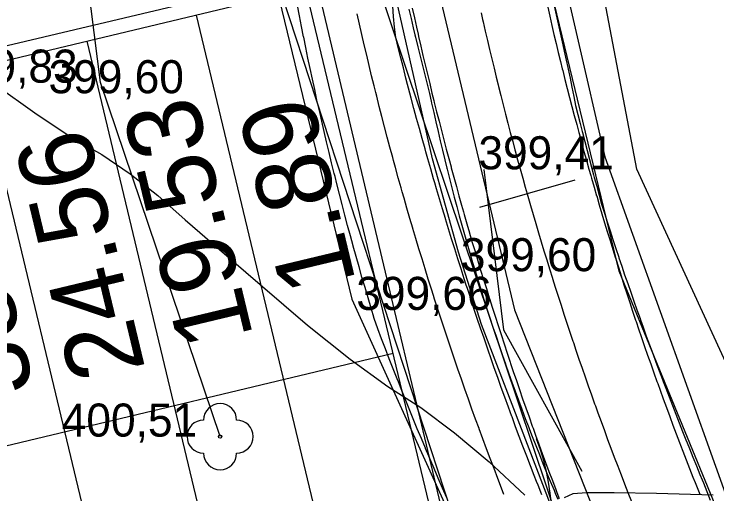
# Model space of a CAD drawing. Extents: x -574342 to -507939, y -1144044 to -1123894.
# Drawn here: x -508553.2 to -508531.96, y -1143248.56 to -1143234.06 of the extents above; entities that cross this region are included whole.
import ezdxf

# ---------------------------------------------------------------- set-up
doc = ezdxf.new("R2010")
doc.units = 0
for name, color, linetype in [('01_PARCELY_NAVRH_PC', 7, 'Continuous'), ('01_PARCELY_NAVRH_VHO', 7, 'Continuous'), ('01_PARCELY_NAVRH_ŽP', 7, 'Continuous'), ('1000', 7, 'Continuous'), ('21', 7, 'Continuous'), ('37', 7, 'Continuous'), ('42', 7, 'Continuous'), ('54', 7, 'Continuous'), ('55', 7, 'Continuous'), ('6', 7, 'Continuous'), ('62', 7, 'Continuous'), ('cesty', 7, 'Continuous'), ('Level 255', 7, 'Continuous'), ('SO 101_popis oblouku', 7, 'Continuous'), ('tab', 7, 'Continuous'), ('VRST HL', 7, 'Continuous')]:
    doc.layers.add(name, color=color, linetype=linetype)

msp = doc.modelspace()

# ---------------------------------------------------------------- linework, layer by layer
msp.add_lwpolyline([(-508538.692, -1143255.691), (-508544.119, -1143232.805), (-508565.304, -1143237.829), (-508559.878, -1143260.714)], close=True)
at = {"layer": '01_PARCELY_NAVRH_PC'}
msp.add_lwpolyline([(-508524.61, -1143277.77), (-508531.94, -1143260.32), (-508534.5, -1143254.93), (-508536.24, -1143250.83), (-508539.07, -1143243.44), (-508539.77, -1143241.25), (-508540.55, -1143238.43), (-508542.83, -1143228.38), (-508544.32, -1143217.47), (-508545.45, -1143205.07), (-508545.52, -1143198.58), (-508545.24, -1143191.32), (-508544.97, -1143188.3), (-508544.25, -1143181.83), (-508541.94, -1143173.53), (-508537.18, -1143176.51), (-508538.65, -1143182.46), (-508540.32, -1143193.28), (-508540.02, -1143209.35), (-508538.46, -1143221.35), (-508537.02, -1143231.11), (-508535.34, -1143238.37), (-508531.16, -1143250.06), (-508524.26, -1143263.08)], dxfattribs=at)
msp.add_lwpolyline([(-508524.61, -1143277.77), (-508531.94, -1143260.32), (-508534.5, -1143254.93), (-508536.24, -1143250.83), (-508539.07, -1143243.44), (-508539.77, -1143241.25), (-508540.55, -1143238.43), (-508542.83, -1143228.38), (-508544.32, -1143217.47), (-508545.45, -1143205.07), (-508545.52, -1143198.58), (-508545.24, -1143191.32), (-508544.97, -1143188.3), (-508544.25, -1143181.83), (-508541.94, -1143173.53), (-508537.18, -1143176.51), (-508538.65, -1143182.46), (-508540.32, -1143193.28), (-508540.02, -1143209.35), (-508538.46, -1143221.35), (-508537.02, -1143231.11), (-508535.34, -1143238.37), (-508531.16, -1143250.06), (-508524.26, -1143263.08)], dxfattribs=at)
at = {"layer": '01_PARCELY_NAVRH_VHO'}
msp.add_lwpolyline([(-508536.24, -1143250.83), (-508539.07, -1143243.44), (-508539.77, -1143241.25), (-508540.55, -1143238.43), (-508542.83, -1143228.38), (-508544.32, -1143217.47), (-508545.45, -1143205.07), (-508545.52, -1143198.58), (-508545.24, -1143191.32), (-508544.97, -1143188.3), (-508544.25, -1143181.83), (-508551.68, -1143170.14), (-508558.5, -1143170.32), (-508555.03, -1143173.64), (-508548.66, -1143186.8), (-508549.63, -1143198.15), (-508549.79, -1143203.71), (-508547.53, -1143223.9), (-508542.99, -1143242.68), (-508538.24, -1143253.15)], close=True, dxfattribs=at)
at = {"layer": '01_PARCELY_NAVRH_ŽP'}
msp.add_lwpolyline([(-508555.03, -1143173.64), (-508548.66, -1143186.8), (-508549.63, -1143198.15), (-508549.79, -1143203.71), (-508547.53, -1143223.9), (-508542.99, -1143242.68), (-508538.24, -1143253.15), (-508539.95, -1143255.3), (-508547.25, -1143258.62), (-508651.11, -1143191.46), (-508662.59, -1143152.85), (-508637.59, -1143153.08), (-508621.09, -1143158.13), (-508610.87, -1143164.96), (-508585.59, -1143176.01), (-508569.25, -1143175.97)], close=True, dxfattribs=at)
at = {"layer": '1000'}
for points in [[(-508540.12, -1143248.685), (-508540.25, -1143248.387), (-508540.379, -1143248.089), (-508540.507, -1143247.79), (-508540.634, -1143247.491), (-508540.761, -1143247.192), (-508540.765, -1143247.182), (-508540.886, -1143246.892), (-508541.011, -1143246.592), (-508541.134, -1143246.291), (-508541.257, -1143245.99), (-508541.379, -1143245.689), (-508541.5, -1143245.387), (-508541.584, -1143245.176), (-508541.621, -1143245.085), (-508541.74, -1143244.782), (-508541.858, -1143244.479), (-508541.976, -1143244.175), (-508542.092, -1143243.871), (-508542.208, -1143243.567), (-508542.315, -1143243.26), (-508542.349, -1143243.147), (-508542.409, -1143242.948), (-508542.501, -1143242.636), (-508542.592, -1143242.324), (-508542.683, -1143242.012), (-508542.772, -1143241.699), (-508542.86, -1143241.386), (-508542.947, -1143241.073), (-508542.949, -1143241.064), (-508543.032, -1143240.759), (-508543.117, -1143240.445), (-508543.2, -1143240.131), (-508543.251, -1143239.937), (-508543.282, -1143239.816), (-508543.364, -1143239.501), (-508543.444, -1143239.186), (-508543.498, -1143238.968), (-508543.523, -1143238.871), (-508543.6, -1143238.555), (-508543.677, -1143238.239), (-508543.752, -1143237.923), (-508543.827, -1143237.607), (-508543.9, -1143237.29), (-508543.972, -1143236.974), (-508543.998, -1143236.861), (-508544.043, -1143236.657), (-508544.113, -1143236.339), (-508544.182, -1143236.022), (-508544.249, -1143235.704), (-508544.316, -1143235.386), (-508544.381, -1143235.068), (-508544.445, -1143234.75), (-508544.447, -1143234.743), (-508544.508, -1143234.431), (-508544.57, -1143234.112), (-508544.631, -1143233.793)], [(-508537.248, -1143248.595), (-508537.28, -1143248.512), (-508537.364, -1143248.301), (-508537.406, -1143248.192), (-508537.479, -1143248.007), (-508537.593, -1143247.712), (-508537.706, -1143247.418), (-508537.818, -1143247.122), (-508537.929, -1143246.827), (-508538.04, -1143246.531), (-508538.15, -1143246.235), (-508538.154, -1143246.225), (-508538.259, -1143245.939), (-508538.367, -1143245.642), (-508538.474, -1143245.345), (-508538.58, -1143245.048), (-508538.685, -1143244.75), (-508538.79, -1143244.452), (-508538.862, -1143244.243), (-508538.893, -1143244.154), (-508538.996, -1143243.855), (-508539.098, -1143243.556), (-508539.199, -1143243.257), (-508539.299, -1143242.957), (-508539.398, -1143242.657), (-508539.496, -1143242.357), (-508539.532, -1143242.248), (-508539.594, -1143242.057), (-508539.69, -1143241.756), (-508539.786, -1143241.455), (-508539.88, -1143241.154), (-508539.974, -1143240.852), (-508540.067, -1143240.551), (-508540.159, -1143240.248), (-508540.162, -1143240.24), (-508540.25, -1143239.946), (-508540.341, -1143239.643), (-508540.43, -1143239.34), (-508540.485, -1143239.154), (-508540.519, -1143239.037), (-508540.606, -1143238.734), (-508540.693, -1143238.43), (-508540.752, -1143238.219), (-508540.779, -1143238.126), (-508540.864, -1143237.822), (-508540.948, -1143237.517), (-508541.031, -1143237.212), (-508541.113, -1143236.907), (-508541.194, -1143236.602), (-508541.274, -1143236.296), (-508541.303, -1143236.187), (-508541.354, -1143235.99), (-508541.432, -1143235.684), (-508541.51, -1143235.378), (-508541.587, -1143235.071), (-508541.663, -1143234.765), (-508541.7, -1143234.449), (-508541.727, -1143234.131), (-508541.727, -1143234.125), (-508541.75, -1143233.813)], [(-508541.266, -1143233.904), (-508541.2, -1143234.189), (-508541.134, -1143234.474), (-508541.085, -1143234.681), (-508541.067, -1143234.759), (-508540.999, -1143235.043), (-508540.93, -1143235.328), (-508540.859, -1143235.612), (-508540.789, -1143235.895), (-508540.717, -1143236.179), (-508540.644, -1143236.462), (-508540.59, -1143236.693), (-508540.578, -1143236.747), (-508540.515, -1143237.033), (-508540.451, -1143237.319), (-508540.386, -1143237.604), (-508540.319, -1143237.889), (-508540.252, -1143238.173), (-508540.182, -1143238.458), (-508540.119, -1143238.713), (-508540.112, -1143238.742), (-508540.041, -1143239.026), (-508539.968, -1143239.309), (-508539.894, -1143239.592), (-508539.818, -1143239.875), (-508539.763, -1143240.079), (-508539.742, -1143240.158), (-508539.664, -1143240.44), (-508539.586, -1143240.717), (-508539.585, -1143240.722), (-508539.505, -1143241.003), (-508539.423, -1143241.284), (-508539.34, -1143241.565), (-508539.256, -1143241.845), (-508539.171, -1143242.125), (-508539.085, -1143242.405), (-508538.997, -1143242.684), (-508538.991, -1143242.704), (-508538.908, -1143242.963), (-508538.817, -1143243.241), (-508538.725, -1143243.519), (-508538.632, -1143243.797), (-508538.539, -1143244.074), (-508538.445, -1143244.351), (-508538.35, -1143244.628), (-508538.335, -1143244.671), (-508538.252, -1143244.904), (-508538.154, -1143245.18), (-508538.054, -1143245.455), (-508537.953, -1143245.73), (-508537.851, -1143246.004), (-508537.748, -1143246.278), (-508537.643, -1143246.551), (-508537.618, -1143246.617), (-508537.538, -1143246.824), (-508537.431, -1143247.097), (-508537.323, -1143247.369), (-508537.214, -1143247.64), (-508537.104, -1143247.911), (-508536.992, -1143248.182), (-508536.88, -1143248.452), (-508536.843, -1143248.54), (-508536.766, -1143248.721)], [(-508541.163, -1143233.882), (-508541.1, -1143234.167), (-508541.037, -1143234.452), (-508540.99, -1143234.659), (-508540.972, -1143234.737), (-508540.907, -1143235.022), (-508540.841, -1143235.307), (-508540.774, -1143235.591), (-508540.706, -1143235.876), (-508540.638, -1143236.16), (-508540.569, -1143236.444), (-508540.512, -1143236.674), (-508540.498, -1143236.727), (-508540.427, -1143237.011), (-508540.356, -1143237.294), (-508540.283, -1143237.577), (-508540.21, -1143237.86), (-508540.135, -1143238.143), (-508540.06, -1143238.425), (-508539.992, -1143238.678), (-508539.985, -1143238.707), (-508539.908, -1143238.989), (-508539.83, -1143239.271), (-508539.752, -1143239.553), (-508539.673, -1143239.834), (-508539.616, -1143240.037), (-508539.593, -1143240.115), (-508539.513, -1143240.396), (-508539.433, -1143240.672), (-508539.431, -1143240.677), (-508539.349, -1143240.957), (-508539.266, -1143241.237), (-508539.182, -1143241.517), (-508539.097, -1143241.797), (-508539.012, -1143242.076), (-508538.925, -1143242.356), (-508538.838, -1143242.635), (-508538.832, -1143242.654), (-508538.75, -1143242.913), (-508538.662, -1143243.192), (-508538.572, -1143243.47), (-508538.482, -1143243.748), (-508538.391, -1143244.026), (-508538.299, -1143244.303), (-508538.206, -1143244.58), (-508538.192, -1143244.623), (-508538.113, -1143244.857), (-508538.019, -1143245.134), (-508537.924, -1143245.41), (-508537.828, -1143245.686), (-508537.731, -1143245.962), (-508537.634, -1143246.237), (-508537.536, -1143246.513), (-508537.512, -1143246.579), (-508537.437, -1143246.788), (-508537.337, -1143247.062), (-508537.236, -1143247.337), (-508537.135, -1143247.611), (-508537.033, -1143247.885), (-508536.93, -1143248.158), (-508536.826, -1143248.431), (-508536.792, -1143248.52), (-508536.722, -1143248.704)], [(-508537.072, -1143233.85), (-508537.009, -1143234.123), (-508536.946, -1143234.397), (-508536.882, -1143234.67), (-508536.817, -1143234.943), (-508536.751, -1143235.216), (-508536.684, -1143235.489), (-508536.63, -1143235.71), (-508536.617, -1143235.761), (-508536.549, -1143236.034), (-508536.48, -1143236.306), (-508536.41, -1143236.578), (-508536.339, -1143236.85), (-508536.268, -1143237.121), (-508536.196, -1143237.393), (-508536.131, -1143237.636), (-508536.123, -1143237.664), (-508536.049, -1143237.935), (-508535.975, -1143238.206), (-508535.9, -1143238.476), (-508535.824, -1143238.746), (-508535.769, -1143238.941), (-508535.747, -1143239.016), (-508535.67, -1143239.286), (-508535.593, -1143239.551), (-508535.591, -1143239.556), (-508535.512, -1143239.825), (-508535.432, -1143240.095), (-508535.352, -1143240.364), (-508535.27, -1143240.632), (-508535.188, -1143240.901), (-508535.105, -1143241.169), (-508535.022, -1143241.437), (-508535.016, -1143241.455), (-508534.937, -1143241.705), (-508534.852, -1143241.972), (-508534.766, -1143242.24), (-508534.679, -1143242.507), (-508534.592, -1143242.773), (-508534.504, -1143243.04), (-508534.415, -1143243.306), (-508534.401, -1143243.347), (-508534.325, -1143243.572), (-508534.234, -1143243.838), (-508534.143, -1143244.104), (-508534.051, -1143244.369), (-508533.958, -1143244.634), (-508533.864, -1143244.899), (-508533.77, -1143245.163), (-508533.747, -1143245.227), (-508533.675, -1143245.427), (-508533.579, -1143245.691), (-508533.482, -1143245.955), (-508533.385, -1143246.218), (-508533.287, -1143246.481), (-508533.188, -1143246.744), (-508533.088, -1143247.006), (-508533.056, -1143247.092), (-508532.988, -1143247.269), (-508532.887, -1143247.531), (-508532.785, -1143247.792), (-508532.682, -1143248.054), (-508532.618, -1143248.216), (-508532.579, -1143248.315), (-508532.475, -1143248.575)], [(-508536.872, -1143233.804), (-508536.814, -1143234.078), (-508536.755, -1143234.352), (-508536.696, -1143234.626), (-508536.635, -1143234.9), (-508536.574, -1143235.173), (-508536.513, -1143235.447), (-508536.462, -1143235.669), (-508536.451, -1143235.72), (-508536.396, -1143235.995), (-508536.341, -1143236.271), (-508536.285, -1143236.546), (-508536.229, -1143236.821), (-508536.161, -1143237.093), (-508536.092, -1143237.365), (-508536.03, -1143237.609), (-508536.022, -1143237.637), (-508535.952, -1143237.908), (-508535.881, -1143238.18), (-508535.809, -1143238.451), (-508535.737, -1143238.722), (-508535.684, -1143238.917), (-508535.664, -1143238.993), (-508535.59, -1143239.263), (-508535.517, -1143239.529), (-508535.516, -1143239.534), (-508535.441, -1143239.804), (-508535.36, -1143240.073), (-508535.274, -1143240.34), (-508535.188, -1143240.607), (-508535.101, -1143240.874), (-508535.014, -1143241.14), (-508534.925, -1143241.407), (-508534.919, -1143241.425), (-508534.836, -1143241.673), (-508534.746, -1143241.938), (-508534.654, -1143242.203), (-508534.562, -1143242.468), (-508534.469, -1143242.733), (-508534.376, -1143242.998), (-508534.282, -1143243.262), (-508534.267, -1143243.303), (-508534.187, -1143243.526), (-508534.092, -1143243.789), (-508533.996, -1143244.053), (-508533.899, -1143244.316), (-508533.801, -1143244.579), (-508533.703, -1143244.841), (-508533.604, -1143245.104), (-508533.581, -1143245.167), (-508533.505, -1143245.366), (-508533.405, -1143245.628), (-508533.304, -1143245.889), (-508533.203, -1143246.15), (-508533.101, -1143246.411), (-508532.998, -1143246.672), (-508532.894, -1143246.932), (-508532.86, -1143247.017), (-508532.79, -1143247.193), (-508532.686, -1143247.452), (-508532.58, -1143247.712), (-508532.474, -1143247.971), (-508532.408, -1143248.133), (-508532.368, -1143248.231), (-508532.264, -1143248.491), (-508532.158, -1143248.75)]]:
    msp.add_lwpolyline(points, dxfattribs=at)
at = {"layer": '21'}
for points in [[(-508538.392, -1143248.577), (-508538.465, -1143248.39), (-508538.58, -1143248.092), (-508538.694, -1143247.794), (-508538.807, -1143247.496), (-508538.919, -1143247.197), (-508539.031, -1143246.898), (-508539.141, -1143246.598), (-508539.145, -1143246.588), (-508539.25, -1143246.299), (-508539.359, -1143245.998), (-508539.466, -1143245.698), (-508539.573, -1143245.397), (-508539.678, -1143245.096), (-508539.783, -1143244.794), (-508539.855, -1143244.584), (-508539.886, -1143244.493), (-508539.989, -1143244.19), (-508540.091, -1143243.888), (-508540.191, -1143243.585), (-508540.291, -1143243.282), (-508540.39, -1143242.979), (-508540.488, -1143242.675), (-508540.523, -1143242.564), (-508540.584, -1143242.371), (-508540.68, -1143242.066), (-508540.775, -1143241.762), (-508540.869, -1143241.457), (-508540.962, -1143241.151), (-508541.054, -1143240.846), (-508541.145, -1143240.54), (-508541.147, -1143240.531), (-508541.235, -1143240.234), (-508541.324, -1143239.927), (-508541.412, -1143239.62), (-508541.466, -1143239.431), (-508541.499, -1143239.313), (-508541.585, -1143239.006), (-508541.67, -1143238.699), (-508541.728, -1143238.486), (-508541.754, -1143238.391), (-508541.837, -1143238.083), (-508541.92, -1143237.774), (-508542.001, -1143237.466), (-508542.081, -1143237.157), (-508542.16, -1143236.848), (-508542.238, -1143236.538), (-508542.266, -1143236.428), (-508542.316, -1143236.229), (-508542.392, -1143235.919), (-508542.467, -1143235.609), (-508542.541, -1143235.298), (-508542.615, -1143234.988), (-508542.687, -1143234.677), (-508542.758, -1143234.366), (-508542.76, -1143234.359), (-508542.828, -1143234.054)], [(-508539.085, -1143234.014), (-508539.04, -1143234.217), (-508539.022, -1143234.293), (-508538.958, -1143234.573), (-508538.893, -1143234.852), (-508538.828, -1143235.131), (-508538.762, -1143235.409), (-508538.694, -1143235.688), (-508538.626, -1143235.966), (-508538.571, -1143236.192), (-508538.558, -1143236.244), (-508538.488, -1143236.522), (-508538.418, -1143236.8), (-508538.346, -1143237.078), (-508538.274, -1143237.355), (-508538.202, -1143237.632), (-508538.128, -1143237.909), (-508538.061, -1143238.157), (-508538.054, -1143238.186), (-508537.979, -1143238.462), (-508537.903, -1143238.738), (-508537.826, -1143239.014), (-508537.749, -1143239.29), (-508537.692, -1143239.489), (-508537.67, -1143239.566), (-508537.591, -1143239.841), (-508537.513, -1143240.112), (-508537.511, -1143240.116), (-508537.431, -1143240.391), (-508537.349, -1143240.666), (-508537.267, -1143240.94), (-508537.184, -1143241.215), (-508537.1, -1143241.489), (-508537.015, -1143241.762), (-508536.93, -1143242.036), (-508536.924, -1143242.055), (-508536.844, -1143242.309), (-508536.757, -1143242.582), (-508536.669, -1143242.855), (-508536.581, -1143243.127), (-508536.491, -1143243.399), (-508536.401, -1143243.671), (-508536.31, -1143243.943), (-508536.296, -1143243.985), (-508536.219, -1143244.215), (-508536.126, -1143244.486), (-508536.033, -1143244.757), (-508535.939, -1143245.027), (-508535.845, -1143245.298), (-508535.749, -1143245.568), (-508535.653, -1143245.838), (-508535.629, -1143245.903), (-508535.556, -1143246.107), (-508535.458, -1143246.377), (-508535.359, -1143246.646), (-508535.26, -1143246.914), (-508535.16, -1143247.183), (-508535.059, -1143247.451), (-508534.957, -1143247.719), (-508534.924, -1143247.806), (-508534.855, -1143247.986), (-508534.752, -1143248.254), (-508534.648, -1143248.521), (-508534.543, -1143248.787)]]:
    msp.add_lwpolyline(points, dxfattribs=at)
at = {"layer": '37'}
for points in [[(-508544.44, -1143182.59), (-508545.29, -1143193.14), (-508544.8, -1143205.6), (-508541.6, -1143228.19), (-508538.07, -1143243), (-508531.89, -1143258.66), (-508522.3, -1143275.29), (-508518.1, -1143283.75), (-508512.73, -1143299.25), (-508510.49, -1143313.12)], [(-508544.44, -1143182.59), (-508545.29, -1143193.14), (-508544.8, -1143205.6), (-508541.6, -1143228.19), (-508538.07, -1143243), (-508531.89, -1143258.66), (-508522.3, -1143275.29), (-508518.1, -1143283.75), (-508512.73, -1143299.25), (-508510.49, -1143313.12)], [(-508507.09, -1143312.37), (-508509.64, -1143298.16), (-508515.1, -1143282.44), (-508519.8, -1143273.76), (-508526.92, -1143261.04), (-508530.09, -1143253.58), (-508534.91, -1143241.83), (-508538.52, -1143226.92), (-508541.3, -1143204.98), (-508541.88, -1143193.39), (-508540.68, -1143183.59)], [(-508507.09, -1143312.37), (-508509.64, -1143298.16), (-508515.1, -1143282.44), (-508519.8, -1143273.76), (-508526.92, -1143261.04), (-508530.09, -1143253.58), (-508534.91, -1143241.83), (-508538.52, -1143226.92), (-508541.3, -1143204.98), (-508541.88, -1143193.39), (-508540.68, -1143183.59)]]:
    msp.add_lwpolyline(points, dxfattribs=at)
at = {"layer": '42'}
msp.add_lwpolyline([(-508475.71, -1143257.35), (-508496.39, -1143258.35), (-508520.72, -1143253.86), (-508528.66, -1143251.18), (-508534.38, -1143238.75), (-508538.15, -1143218.95), (-508538.33, -1143193.52)], dxfattribs=at)
msp.add_lwpolyline([(-508475.71, -1143257.35), (-508496.39, -1143258.35), (-508520.72, -1143253.86), (-508528.66, -1143251.18), (-508534.38, -1143238.75), (-508538.15, -1143218.95), (-508538.33, -1143193.52)], dxfattribs=at)
at = {"layer": '54'}
msp.add_circle((-508546.97, -1143246.83), 0.05, dxfattribs=at)
for centre, start, end in [((-508546.97, -1143246.33), 0, 180), ((-508547.47, -1143246.83), 90, 270), ((-508546.47, -1143246.83), 270, 90), ((-508546.97, -1143247.33), 180, 0)]:
    msp.add_arc(centre, 0.5, start, end, dxfattribs=at)
at = {"layer": '55'}
msp.add_line((-508539.2, -1143251.47), (-508547.83, -1143225.16), dxfattribs=at)
msp.add_line((-508539.2, -1143251.47), (-508547.83, -1143225.16), dxfattribs=at)
msp.add_lwpolyline([(-508546.97, -1143246.83), (-508550.58, -1143236.13), (-508552.49, -1143221.08)], dxfattribs=at)
msp.add_lwpolyline([(-508546.97, -1143246.83), (-508550.58, -1143236.13), (-508552.49, -1143221.08)], dxfattribs=at)
at = {"layer": '6'}
for points in [[(-508536.25, -1143239.078), (-508539.135, -1143239.9)], [(-508537.692, -1143239.489), (-508537.692, -1143239.489)]]:
    msp.add_lwpolyline(points, dxfattribs=at)
at = {"layer": '62'}
msp.add_lwpolyline([(-508535.82, -1143252.17), (-508543.49, -1143229.3), (-508544.91, -1143218.28), (-508546.55, -1143206.05), (-508547.23, -1143192.43), (-508546.71, -1143185.69)], dxfattribs=at)
msp.add_lwpolyline([(-508535.82, -1143252.17), (-508543.49, -1143229.3), (-508544.91, -1143218.28), (-508546.55, -1143206.05), (-508547.23, -1143192.43), (-508546.71, -1143185.69)], dxfattribs=at)
at = {"layer": 'cesty'}
msp.add_arc((-508543.938, -1143249.426), 7, 294.5203, 21.1483, dxfattribs=at)
at = {"layer": 'SO 101_popis oblouku'}
for p, q in [((-508544.379, -1143233.297), (-508560.912, -1143237.254)), ((-508539.103, -1143255.341), (-508544.379, -1143233.297)), ((-508542.409, -1143256.132), (-508547.685, -1143234.088)), ((-508545.716, -1143256.924), (-508550.992, -1143234.88)), ((-508549.023, -1143257.715), (-508554.299, -1143235.671)), ((-508541.741, -1143244.319), (-508558.274, -1143248.276))]:
    msp.add_line(p, q, dxfattribs=at)
at = {"layer": 'tab'}
msp.add_lwpolyline([(-508539.004, -1143238.759), (-508538.412, -1143243.606), (-508536.04, -1143247.873)], dxfattribs=at)
at = {"layer": 'VRST HL'}
for points in [[(-508553.803, -1143236.162), (-508552.501, -1143237.09), (-508551.416, -1143237.804), (-508550.547, -1143238.305), (-508549.691, -1143238.883), (-508548.85, -1143239.541), (-508548.022, -1143240.277), (-508546.992, -1143241.175), (-508545.761, -1143242.235), (-508544.327, -1143243.458), (-508543.041, -1143244.485), (-508541.902, -1143245.317), (-508540.91, -1143245.955), (-508539.889, -1143246.714), (-508538.839, -1143247.596), (-508537.76, -1143248.599)], [(-508536.567, -1143248.675), (-508536.302, -1143248.545), (-508535.899, -1143248.523), (-508535.061, -1143248.523), (-508533.786, -1143248.544), (-508532.075, -1143248.587)]]:
    msp.add_lwpolyline(points, dxfattribs=at)

# ---------------------------------------------------------------- texts
at = {"layer": 'Level 255'}
for s, p in [('399,83', (-508555.365, -1143236.13)), ('399,60', (-508552.155, -1143236.45)), ('399,41', (-508539.165, -1143238.75)), ('399,60', (-508539.695, -1143241.83)), ('399,66', (-508542.855, -1143243)), ('400,51', (-508551.755, -1143246.83))]:
    msp.add_text(s, height=1, dxfattribs=at).set_placement(p)
at = {"layer": 'SO 101_popis oblouku'}
for s, p in [('19.53', (-508545.962, -1143243.818)), ('1.89', (-508542.863, -1143242.16)), ('24.56', (-508549.226, -1143244.786)), ('38.57', (-508552.575, -1143245.401))]:
    msp.add_text(s, height=2.2667, rotation=103.4546, dxfattribs=at).set_placement(p)

doc.saveas('drawing.dxf')
